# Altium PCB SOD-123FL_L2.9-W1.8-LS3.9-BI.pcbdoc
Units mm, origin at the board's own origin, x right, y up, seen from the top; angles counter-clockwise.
Board outline 17 x 14.56 mm, 2 copper layers (Top Layer, Bottom Layer), stack 0 mm thick; 1 components, 0 nets, 2 pads, 0 vias.
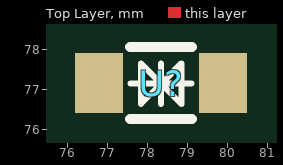
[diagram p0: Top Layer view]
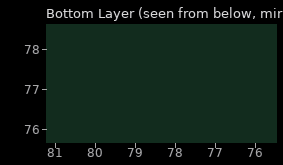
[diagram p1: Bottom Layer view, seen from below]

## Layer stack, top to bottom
Top Layer: signal copper (thickness not stored)
Bottom Layer: signal copper (thickness not stored)

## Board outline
86.85,69.85 69.85,69.85 69.85,84.41 86.85,84.41

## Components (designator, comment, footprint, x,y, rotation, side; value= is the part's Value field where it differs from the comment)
U? "" SOD-123FL_L2.9-W1.8-LS3.9-BI 78.35,77.16 r0 top

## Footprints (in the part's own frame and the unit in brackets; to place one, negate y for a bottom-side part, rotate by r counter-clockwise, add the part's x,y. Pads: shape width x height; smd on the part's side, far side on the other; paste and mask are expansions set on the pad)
SOD-123FL_L2.9-W1.8-LS3.9-BI [mm]
  rect 1.2x1.5 smd paste+0 mask+0.05: 1(-1.55,0) 2(1.55,0)
  silkscreen extent -0.77,-0.9 0.77,0.9

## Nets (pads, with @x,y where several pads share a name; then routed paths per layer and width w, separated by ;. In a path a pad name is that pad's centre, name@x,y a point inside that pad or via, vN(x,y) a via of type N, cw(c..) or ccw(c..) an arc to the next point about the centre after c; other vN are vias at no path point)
pads on no net: U?.1 U?.2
